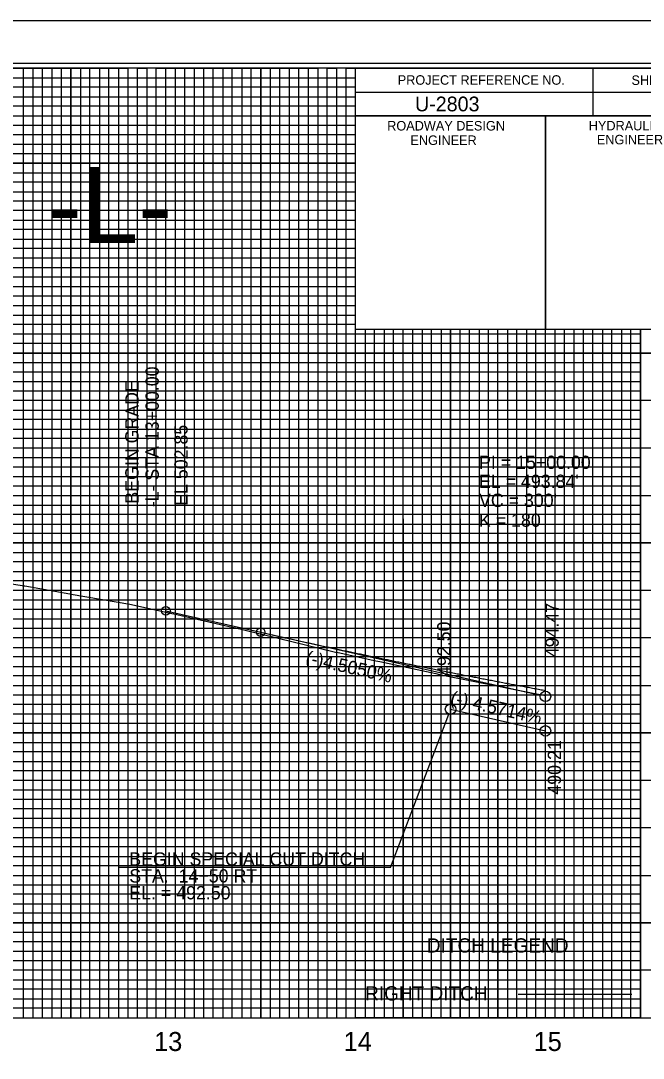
# Model space of a CAD drawing. Extents: x 571503 to 593215, y -77195 to -51828.
# Drawn here: x 583621 to 583949, y -71929 to -71383 of the extents above; entities that cross this region are included whole.
import ezdxf

# ---------------------------------------------------------------- set-up
doc = ezdxf.new("R2010")
doc.units = 0
for name, color, linetype in [('Exist Vertical Profile Ground Line', 7, 'Continuous'), ('Exist Vertical Profile Horizontal Axis Label Major', 7, 'Continuous'), ('Exist Vertical Profile Vertical Axis Label', 7, 'Continuous'), ('Prop Grid Mask', 7, 'Continuous'), ('Prop PFL Ditch Label CELL', 7, 'Continuous'), ('Prop PFL Text', 7, 'Continuous'), ('Prop Vertical Profile Curve Label', 7, 'Continuous'), ('Prop Vertical Profile Ditch Grade Right', 7, 'Continuous'), ('Prop Vertical Profile Ditch Grade Right Label', 7, 'Continuous'), ('Prop Vertical Profile Grade', 7, 'Continuous'), ('Prop Vertical Profile Grade Label', 7, 'Continuous'), ('Prop VPI Ditch Grade Right Label', 7, 'Continuous'), ('Prop VPI Label', 7, 'Continuous'), ('Sheet Cutting Line CELL', 7, 'Continuous'), ('Sheet Data Field CELL', 7, 'Continuous'), ('Sheet DOT Grid CELL', 7, 'Continuous'), ('Sheet Layout Profile Border Port 1', 7, 'Continuous'), ('Sheet Plot Border Inside CELL', 7, 'Continuous'), ('Sheet Plot Border Outside CELL', 7, 'Continuous'), ('Sheet Profile CELL', 7, 'Continuous'), ('Sheet Profile Grid Major CELL', 7, 'Continuous'), ('Sheet Profile Grid Middle CELL', 7, 'Continuous'), ('Sheet Profile Grid Minor CELL', 7, 'Continuous')]:
    doc.layers.add(name, color=color, linetype=linetype)

msp = doc.modelspace()

# ---------------------------------------------------------------- linework, layer by layer
at = {"layer": 'Exist Vertical Profile Ground Line'}
msp.add_lwpolyline([(583590.76, -71675.24), (583622.34, -71680.43), (583622.66, -71680.48), (583646.4, -71684.59), (583647.12, -71684.71), (583678.09, -71690.06), (583678.86, -71690.19), (583700.09, -71694.95), (583701.25, -71695.22), (583731.97, -71702.1), (583732.96, -71702.33), (583754.7, -71707.6), (583756.25, -71707.97), (583786.4, -71715.27), (583787.69, -71715.58), (583807.59, -71719.84), (583809.78, -71720.32), (583839.27, -71726.62), (583841.09, -71727.02), (583843.8, -71727.58), (583873.07, -71733.49), (583874.65, -71733.81), (583891.35, -71737.18), (583896.98, -71738.23)], dxfattribs=at)
at = {"layer": 'Prop Grid Mask'}
for points in [[(583796.98, -71857.85), (583946.98, -71857.85), (583946.98, -71882.85), (583796.98, -71882.85)], [(583796.98, -71882.85), (583946.98, -71882.85), (583946.98, -71907.85), (583796.98, -71907.85)]]:
    msp.add_lwpolyline(points, close=True, dxfattribs=at)
at = {"layer": 'Prop PFL Ditch Label CELL'}
for p, q in [((583882.53, -71895.5), (583942.53, -71895.5)), ((583796.98, -71897.85), (583796.98, -71897.85))]:
    msp.add_line(p, q, dxfattribs=at)
at = {"layer": 'Prop PFL Text'}
msp.add_line((583696.98, -71693.6), (583696.98, -71547.21), dxfattribs=at)
at = {"layer": 'Prop Vertical Profile Curve Label'}
for centre in [(583696.98, -71693.6), (583746.98, -71704.86)]:
    msp.add_circle(centre, 2.25, dxfattribs=at)
at = {"layer": 'Prop Vertical Profile Ditch Grade Right'}
msp.add_line((583846.98, -71745.35), (583896.98, -71756.78), dxfattribs=at)
at = {"layer": 'Prop Vertical Profile Grade'}
msp.add_line((583696.98, -71693.6), (583746.98, -71704.86), dxfattribs=at)
msp.add_spline([(583746.98, -71704.86), (583749.98, -71705.53), (583752.98, -71706.2), (583755.98, -71706.87), (583758.98, -71707.54), (583761.98, -71708.2), (583764.98, -71708.86), (583767.98, -71709.52), (583770.98, -71710.18), (583773.98, -71710.83), (583776.98, -71711.48), (583779.98, -71712.13), (583782.98, -71712.78), (583785.98, -71713.42), (583788.98, -71714.07), (583791.98, -71714.71), (583794.98, -71715.34), (583797.98, -71715.98), (583800.98, -71716.61), (583803.98, -71717.24), (583806.98, -71717.86), (583809.98, -71718.49), (583812.98, -71719.11), (583815.98, -71719.73), (583818.98, -71720.35), (583821.98, -71720.96), (583824.98, -71721.57), (583827.98, -71722.18), (583830.98, -71722.79), (583833.98, -71723.39), (583836.98, -71723.99), (583839.98, -71724.59), (583842.98, -71725.19), (583845.98, -71725.78), (583848.98, -71726.38), (583851.98, -71726.97), (583854.98, -71727.55), (583857.98, -71728.14), (583860.98, -71728.72), (583863.98, -71729.3), (583866.98, -71729.88), (583869.98, -71730.45), (583872.98, -71731.02), (583875.98, -71731.59), (583878.98, -71732.16), (583881.98, -71732.72), (583884.98, -71733.28), (583887.98, -71733.84), (583890.98, -71734.4), (583893.98, -71734.95), (583896.98, -71735.51)], degree=3, dxfattribs=at)
at = {"layer": 'Prop VPI Ditch Grade Right Label'}
for q in [(583846.01, -71747.92), (583672.59, -71828.77)]:
    msp.add_line((583815.34, -71828.77), q, dxfattribs=at)
for centre in [(583846.98, -71745.35), (583896.98, -71756.78)]:
    msp.add_circle(centre, 2.75, dxfattribs=at)
at = {"layer": 'Prop VPI Label'}
msp.add_line((583746.98, -71704.86), (583894.3, -71738.02), dxfattribs=at)
msp.add_circle((583896.98, -71738.63), 2.75, dxfattribs=at)
at = {"layer": 'Sheet Cutting Line CELL'}
msp.add_line((584013.98, -71382.85), (582329.98, -71382.85), dxfattribs=at)
at = {"layer": 'Sheet DOT Grid CELL'}
for p, q in [((583646.98, -71907.85), (583646.98, -71407.85)), ((583696.98, -71907.85), (583696.98, -71407.85)), ((583746.98, -71907.85), (583746.98, -71407.85)), ((583796.93, -71457.85), (582496.98, -71457.85)), ((583796.93, -71507.85), (582496.98, -71507.85)), ((583796.98, -71907.85), (583796.98, -71545.4)), ((583846.98, -71907.85), (583846.98, -71545.4)), ((583896.98, -71907.85), (583896.98, -71545.4)), ((583946.98, -71907.85), (583946.98, -71545.4)), ((583996.98, -71557.85), (582496.98, -71557.85)), ((583996.98, -71607.85), (582496.98, -71607.85)), ((583996.98, -71657.85), (582496.98, -71657.85)), ((583996.98, -71707.85), (582496.98, -71707.85)), ((583996.98, -71757.85), (582496.98, -71757.85)), ((583996.98, -71807.85), (582496.98, -71807.85)), ((583996.98, -71857.85), (582496.98, -71857.85))]:
    msp.add_line(p, q, dxfattribs=at)
at = {"layer": 'Sheet Layout Profile Border Port 1'}
msp.add_lwpolyline([(582546.98, -71407.85), (582546.98, -71907.85), (583946.98, -71907.85), (583946.98, -71545.4), (583796.93, -71545.4), (583796.93, -71407.85)], close=True, dxfattribs=at)
at = {"layer": 'Sheet Plot Border Inside CELL'}
msp.add_lwpolyline([(582342.98, -72460.4), (584009.48, -72460.4), (584009.48, -71405.3), (582342.98, -71405.3)], close=True, dxfattribs=at)
at = {"layer": 'Sheet Plot Border Outside CELL'}
msp.add_lwpolyline([(582329.98, -72482.85), (584013.98, -72482.85), (584013.98, -71382.85), (582329.98, -71382.85)], close=True, dxfattribs=at)
at = {"layer": 'Sheet Profile CELL'}
for p, q in [((583921.98, -71407.9), (583921.98, -71432.9)), ((583796.93, -71420.4), (583996.98, -71420.4)), ((583896.98, -71432.9), (583896.98, -71545.35)), ((582496.98, -71907.85), (583996.98, -71907.85))]:
    msp.add_line(p, q, dxfattribs=at)
for points in [[(583996.98, -71407.85), (582496.98, -71407.85), (582496.98, -72457.85), (583996.98, -72457.85)], [(583796.93, -71407.85), (583996.98, -71407.85), (583996.98, -71432.9), (583796.93, -71432.9)], [(583796.93, -71432.9), (583896.98, -71432.9), (583896.98, -71545.4), (583796.93, -71545.4)], [(583896.98, -71432.9), (583996.98, -71432.9), (583996.98, -71545.4), (583896.98, -71545.4)]]:
    msp.add_lwpolyline(points, close=True, dxfattribs=at)
at = {"layer": 'Sheet Profile Grid Major CELL'}
for points in [[(583596.98, -71407.85), (583646.98, -71407.85), (583646.98, -71907.85), (583696.98, -71907.85), (583696.98, -71407.85), (583746.98, -71407.85), (583746.98, -71907.85), (583796.98, -71907.85), (583796.98, -71407.85), (583823.28, -71407.85)], [(582496.98, -71457.85), (583796.98, -71457.85)], [(583796.98, -71507.85), (582496.98, -71507.85), (582496.98, -71557.85), (583996.98, -71557.85)], [(583846.98, -71545.4), (583846.98, -71907.85), (583896.98, -71907.85), (583896.98, -71907.85), (583896.98, -71545.4)], [(583946.98, -71545.4), (583946.98, -71907.85), (583996.98, -71907.85), (583996.98, -71557.85)], [(583996.98, -71607.85), (582496.98, -71607.85), (582496.98, -71657.85), (583996.98, -71657.85)], [(583996.98, -71707.85), (582496.98, -71707.85), (582496.98, -71757.85), (583996.98, -71757.85)], [(583996.98, -71807.85), (582496.98, -71807.85), (582496.98, -71807.85), (582496.98, -71857.85), (583996.98, -71857.85)]]:
    msp.add_lwpolyline(points, dxfattribs=at)
at = {"layer": 'Sheet Profile Grid Middle CELL'}
msp.add_line((582496.98, -71432.85), (583796.93, -71432.85), dxfattribs=at)
for points in [[(583571.98, -71907.85), (583621.98, -71907.85), (583621.98, -71407.85), (583671.98, -71407.85), (583671.98, -71907.85), (583721.98, -71907.85), (583721.98, -71407.85), (583771.98, -71407.85), (583771.98, -71907.85), (583821.98, -71907.85), (583821.98, -71545.4)], [(583796.98, -71482.85), (582496.98, -71482.85), (582496.98, -71532.85), (583796.98, -71532.85)], [(583821.98, -71645.05), (583821.98, -71907.85), (583871.98, -71907.85), (583871.98, -71545.4)], [(583871.98, -71645.05), (583871.98, -71907.85), (583921.98, -71907.85), (583921.98, -71545.4)], [(583996.98, -71582.85), (582496.98, -71582.85), (582496.98, -71632.85), (583821.98, -71632.85)], [(583821.98, -71632.85), (583996.98, -71632.85)], [(583996.98, -71682.85), (582496.98, -71682.85), (582496.98, -71732.85), (583996.98, -71732.85)], [(583996.98, -71782.85), (582496.98, -71782.85), (582496.98, -71832.85), (583996.98, -71832.85)], [(583996.98, -71882.85), (582496.98, -71882.85)]]:
    msp.add_lwpolyline(points, dxfattribs=at)
at = {"layer": 'Sheet Profile Grid Minor CELL'}
for p, q in [((582546.98, -71412.85), (583796.98, -71412.85)), ((583796.98, -71417.85), (582546.98, -71418.2)), ((582546.98, -71422.85), (583796.98, -71422.85)), ((583796.93, -71542.85), (582546.98, -71542.85)), ((583946.98, -71547.85), (582546.98, -71547.85)), ((583946.98, -71552.85), (582546.98, -71552.85)), ((582546.98, -71562.85), (583946.98, -71562.85)), ((583946.98, -71567.85), (582546.98, -71567.85)), ((582546.98, -71572.85), (583946.98, -71572.85)), ((583946.98, -71592.85), (582546.98, -71592.85)), ((582546.98, -71597.85), (583946.98, -71597.85)), ((583946.98, -71617.85), (582546.98, -71617.85)), ((582546.98, -71622.85), (583946.98, -71622.85)), ((583946.98, -71642.85), (582546.98, -71642.85)), ((582546.98, -71647.85), (583946.98, -71647.85)), ((583946.98, -71652.85), (582546.98, -71652.85)), ((582546.98, -71662.85), (583946.98, -71662.85)), ((583946.98, -71667.85), (582546.98, -71667.85)), ((582546.98, -71672.85), (583946.98, -71672.85)), ((583946.98, -71677.85), (582546.98, -71677.85)), ((582546.98, -71687.85), (583946.98, -71687.85)), ((583946.98, -71692.85), (582546.98, -71692.85)), ((582546.98, -71697.85), (583946.98, -71697.85)), ((583946.98, -71702.85), (582546.98, -71702.85)), ((582546.98, -71712.85), (583946.98, -71712.85)), ((583946.98, -71717.85), (582546.98, -71717.85)), ((582546.98, -71722.85), (583946.98, -71722.85)), ((583946.98, -71727.85), (582546.98, -71727.85)), ((582546.98, -71737.85), (583946.98, -71737.85)), ((583946.98, -71742.85), (582546.98, -71742.85)), ((582546.98, -71747.85), (583946.98, -71747.85)), ((583946.98, -71752.85), (582546.98, -71752.85)), ((582546.98, -71762.85), (583946.98, -71762.85)), ((583946.98, -71767.85), (582546.98, -71767.85)), ((582546.98, -71772.85), (583946.98, -71772.85)), ((583946.98, -71777.85), (582546.98, -71777.85)), ((582546.98, -71787.85), (583946.98, -71787.85)), ((583946.98, -71792.85), (582546.98, -71792.85)), ((583946.98, -71797.85), (582546.98, -71797.85)), ((583946.98, -71802.85), (582546.98, -71802.85)), ((582546.98, -71812.85), (583946.98, -71812.85)), ((583946.98, -71817.85), (582546.98, -71817.85)), ((582546.98, -71822.85), (583946.98, -71822.85)), ((583946.98, -71827.85), (582546.98, -71827.85)), ((582546.98, -71837.85), (583946.98, -71837.85)), ((583946.98, -71842.85), (582546.98, -71842.85)), ((582546.98, -71847.85), (583946.98, -71847.85)), ((583946.98, -71852.85), (582546.98, -71852.85)), ((582546.98, -71862.85), (583946.98, -71862.85)), ((583946.98, -71867.85), (582546.98, -71867.85)), ((582546.98, -71872.85), (583946.98, -71872.85)), ((583946.98, -71877.85), (582546.98, -71877.85)), ((582546.98, -71887.85), (583946.98, -71887.85)), ((583946.98, -71892.85), (582546.98, -71892.85)), ((582546.98, -71897.85), (583946.98, -71897.85))]:
    msp.add_line(p, q, dxfattribs=at)
for points in [[(583616.98, -71407.85), (583626.98, -71407.85), (583626.98, -71907.85), (583631.98, -71907.85), (583631.98, -71407.85), (583636.98, -71407.85), (583636.98, -71907.85), (583641.98, -71907.85), (583641.98, -71407.85), (583651.98, -71407.85), (583651.98, -71907.85), (583656.98, -71907.85), (583656.98, -71407.85), (583661.98, -71407.85), (583661.98, -71907.85), (583666.98, -71907.85), (583666.98, -71407.85), (583676.98, -71407.85), (583676.98, -71907.85), (583681.98, -71907.85), (583681.98, -71407.85), (583686.98, -71407.85), (583686.98, -71907.85)], [(583686.98, -71907.85), (583691.98, -71907.85), (583691.98, -71407.85), (583701.98, -71407.85), (583701.98, -71907.85), (583706.98, -71907.85), (583706.98, -71407.85), (583711.98, -71407.85), (583711.98, -71907.85), (583716.98, -71907.85), (583716.98, -71407.85), (583726.98, -71407.85), (583726.98, -71907.85), (583731.98, -71907.85), (583731.98, -71407.85), (583736.98, -71407.85), (583736.98, -71907.85), (583741.98, -71907.85), (583741.98, -71407.85), (583751.98, -71407.85), (583751.98, -71907.85), (583756.98, -71907.85), (583756.98, -71407.85), (583761.98, -71407.85), (583761.98, -71907.85), (583766.98, -71907.85), (583766.98, -71407.85), (583776.98, -71407.85), (583776.98, -71907.85), (583781.98, -71907.85), (583781.98, -71407.85), (583786.98, -71407.85), (583786.98, -71907.85), (583791.98, -71907.85), (583791.98, -71407.85), (583801.98, -71407.85)], [(583796.98, -71427.85), (582546.98, -71427.85), (582546.98, -71437.85), (583796.98, -71437.85)], [(583796.93, -71442.85), (582546.98, -71442.85), (582546.98, -71447.85), (583796.98, -71447.85)], [(583796.98, -71452.85), (582546.98, -71452.85), (582546.98, -71462.85), (583796.98, -71462.85)], [(583796.98, -71467.85), (582546.98, -71467.85), (582546.98, -71472.85), (583796.98, -71472.85)], [(583796.98, -71477.85), (582546.98, -71477.85), (582546.98, -71487.85), (583796.98, -71487.85)], [(583796.98, -71492.85), (582546.98, -71492.85), (582546.98, -71497.85), (583796.98, -71497.85)], [(583796.98, -71502.85), (582546.98, -71502.85), (582546.98, -71512.85), (583796.98, -71512.85)], [(583796.98, -71517.95), (582547.08, -71517.95), (582547.08, -71522.85), (583796.98, -71522.85)], [(583796.98, -71527.85), (582546.98, -71527.85), (582546.98, -71537.85), (583796.98, -71537.85)], [(583801.98, -71545.4), (583801.98, -71907.85), (583806.98, -71907.85), (583806.98, -71545.4)], [(583811.98, -71545.4), (583811.98, -71907.85), (583816.98, -71907.85), (583816.98, -71545.4)], [(583826.98, -71545.4), (583826.98, -71907.85), (583826.98, -71907.85), (583831.98, -71907.85), (583836.98, -71907.85), (583836.98, -71545.4)], [(583831.98, -71545.4), (583831.98, -71907.85)], [(583841.98, -71545.4), (583841.88, -71907.8), (583846.88, -71907.8), (583851.98, -71907.85), (583851.98, -71545.4)], [(583851.98, -71645.05), (583851.98, -71907.85), (583856.98, -71907.85), (583856.98, -71545.4)], [(583861.98, -71545.4), (583861.98, -71907.85), (583866.98, -71907.85), (583866.98, -71545.4)], [(583876.98, -71545.4), (583876.98, -71907.85), (583881.98, -71907.85), (583881.98, -71545.4)], [(583886.98, -71545.4), (583886.98, -71907.85), (583891.98, -71907.85), (583891.98, -71545.4)], [(583901.98, -71545.4), (583901.98, -71907.85), (583906.98, -71907.85), (583906.98, -71545.4)], [(583911.98, -71545.4), (583911.98, -71907.85), (583916.98, -71907.85), (583916.98, -71545.4)], [(583926.98, -71545.4), (583926.98, -71907.85), (583931.98, -71907.85), (583931.98, -71545.4)], [(583936.98, -71545.4), (583936.98, -71907.85), (583941.98, -71907.85), (583941.98, -71545.4)], [(583946.98, -71577.85), (582546.98, -71577.85), (582546.98, -71587.85), (583946.98, -71587.85)], [(583946.98, -71602.85), (582546.98, -71602.85), (582546.98, -71612.85), (583946.98, -71612.85)], [(583946.98, -71627.85), (582546.98, -71627.85), (582546.98, -71637.85), (583946.98, -71637.85)], [(583946.98, -71902.85), (582546.98, -71902.85)]]:
    msp.add_lwpolyline(points, dxfattribs=at)

# ---------------------------------------------------------------- texts
at = {"layer": 'Exist Vertical Profile Horizontal Axis Label Major'}
for s, p in [('13', (583690.79, -71925.35)), ('14', (583790.63, -71925.35)), ('15', (583890.72, -71925.35))]:
    msp.add_text(s, height=10, dxfattribs=at).set_placement(p)
at = {"layer": 'Exist Vertical Profile Vertical Axis Label'}
msp.add_text('-L-', height=40, dxfattribs=at).set_placement((583634.92, -71499.83))
at = {"layer": 'Prop PFL Ditch Label CELL'}
for s, height, p in [('DITCH LEGEND', 7.5, (583834.48, -71873.5)), ('RIGHT DITCH', 7.485, (583801.98, -71898.75))]:
    msp.add_text(s, height=height, dxfattribs=at).set_placement(p)
at = {"layer": 'Prop PFL Text'}
for s, p in [('-L- STA 13+00.00', (583693.27, -71639.04)), ('BEGIN GRADE', (583682.62, -71637.14)), ('EL 502.85', (583708.47, -71638.29))]:
    msp.add_text(s, height=7, rotation=90, dxfattribs=at).set_placement(p)
at = {"layer": 'Prop Vertical Profile Curve Label'}
for s, p in [("VC = 300'", (583861.98, -71638.86)), ('K = 180', (583861.98, -71649.33))]:
    msp.add_text(s, height=7, dxfattribs=at).set_placement(p)
at = {"layer": 'Prop Vertical Profile Ditch Grade Right Label'}
msp.add_text('(-) 4.5714%', height=7, rotation=347.125, dxfattribs=at).set_placement((583846.45, -71742.48))
at = {"layer": 'Prop Vertical Profile Grade Label'}
msp.add_text('(-)4.5050%', height=7, rotation=347.3118, dxfattribs=at).set_placement((583770.2, -71721.37))
at = {"layer": 'Prop VPI Ditch Grade Right Label'}
for s, p in [('492.50', (583846.98, -71727.85)), ('490.21', (583905.19, -71790.36))]:
    msp.add_text(s, height=7, rotation=90, dxfattribs=at).set_placement(p)
for s, p in [('BEGIN SPECIAL CUT DITCH', (583677.73, -71827.76)), ('STA.  14+50 RT', (583677.73, -71836.63)), ('EL. = 492.50', (583677.73, -71845.51))]:
    msp.add_text(s, height=7, dxfattribs=at).set_placement(p)
at = {"layer": 'Prop VPI Label'}
for s, p in [('PI = 15+00.00', (583861.98, -71618.86)), ("EL = 493.84'", (583861.98, -71628.86))]:
    msp.add_text(s, height=7, dxfattribs=at).set_placement(p)
msp.add_text('494.47', height=7, rotation=90, dxfattribs=at).set_placement((583903.98, -71718.01))
at = {"layer": 'Sheet Data Field CELL'}
msp.add_text('U-2803   ', height=7.75, dxfattribs=at).set_placement((583828.25, -71430.54))
at = {"layer": 'Sheet Profile CELL'}
for s, height, p in [('PROJECT REFERENCE NO.', 5.0001, (583819.15, -71416.54)), ('SHEET NO.', 5, (583942.3, -71416.64)), ('ROADWAY DESIGN', 5.0001, (583813.6, -71440.64)), ('HYDRAULICS', 5, (583919.8, -71440.59)), ('ENGINEER', 5, (583825.85, -71448.24)), ('ENGINEER', 5, (583924.05, -71447.94))]:
    msp.add_text(s, height=height, dxfattribs=at).set_placement(p)

doc.saveas('drawing.dxf')
